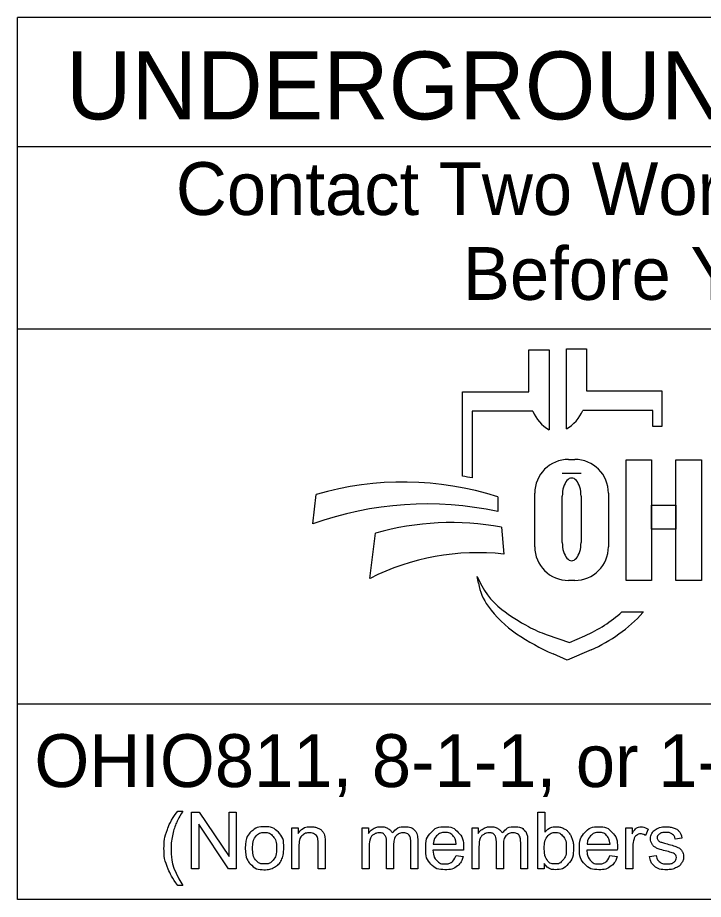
# Model space of a CAD drawing. Extents: x 0 to 72, y -85 to 22.
# Drawn here: x 2.978 to 4.796, y 2.143 to 4.48 of the extents above; entities that cross this region are included whole.
import ezdxf

# ---------------------------------------------------------------- set-up
doc = ezdxf.new("R2010")
doc.units = 0
doc.layers.add('GM_X_Adjacent_County', color=7, linetype='Continuous')
doc.layers.add('GM_X_Township', color=7, linetype='Continuous')

msp = doc.modelspace()

# ---------------------------------------------------------------- linework, layer by layer
at = {"layer": 'GM_X_Adjacent_County'}
for p, q in [((4.3335, 3.4883), (4.3335, 3.5998)), ((4.3335, 3.5998), (4.3872, 3.5998)), ((4.3872, 3.5998), (4.3872, 3.3877)), ((4.4329, 3.39), (4.4329, 3.6021)), ((4.4329, 3.6021), (4.4865, 3.6021)), ((4.4865, 3.6021), (4.4865, 3.4906)), ((4.1576, 3.2644), (4.1576, 3.4883)), ((4.1576, 3.4883), (4.3335, 3.4883)), ((4.4865, 3.4906), (4.6857, 3.4906)), ((4.6857, 3.4906), (4.6857, 3.3968)), ((4.1828, 3.4369), (4.1828, 3.26)), ((4.3439, 3.4369), (4.1828, 3.4369)), ((4.6625, 3.4392), (4.4761, 3.4392)), ((4.6625, 3.3968), (4.6625, 3.4392)), ((4.6857, 3.3968), (4.6625, 3.3968)), ((4.4385, 3.3091), (4.4551, 3.3091)), ((4.4718, 3.2721), (4.422, 3.2721)), ((3.7602, 3.1381), (3.7696, 3.2162)), ((4.2509, 3.2097), (4.2509, 3.1709)), ((4.3491, 3.0776), (4.3491, 3.2196)), ((4.422, 3.089), (4.422, 3.2114)), ((4.4718, 3.2114), (4.4718, 3.089)), ((4.5445, 3.2196), (4.5445, 3.0776)), ((3.912, 2.9936), (3.9267, 3.1137)), ((4.2608, 3.1291), (4.2671, 3.0582)), ((4.1997, 2.9807), (4.1967, 2.9986)), ((4.4551, 2.9882), (4.4385, 2.9882)), ((4.58, 2.9048), (4.6375, 2.9048)), ((4.3816, 2.8444), (4.441, 2.8239)), ((4.441, 2.8239), (4.4821, 2.8417)), ((4.435, 2.7769), (4.3976, 2.7934)), ((4.4983, 2.8044), (4.435, 2.7769))]:
    msp.add_line(p, q, dxfattribs=at)
for points in [[(4.591, 3.3081), (4.6589, 3.3081), (4.6589, 2.9881), (4.591, 2.9881)], [(4.7231, 3.3081), (4.7911, 3.3081), (4.7911, 2.9881), (4.7231, 2.9881)], [(4.6589, 3.1882), (4.7231, 3.1882), (4.7231, 3.1242), (4.6589, 3.1242)]]:
    msp.add_lwpolyline(points, close=True, dxfattribs=at)
for points in [[(3.4021, 2.3766), (3.4153, 2.3766)], [(3.4389, 2.2239), (3.4389, 2.3741), (3.4592, 2.3741), (3.5382, 2.2561), (3.5382, 2.3741), (3.5572, 2.3741), (3.5572, 2.2239), (3.5369, 2.2239), (3.4579, 2.3419), (3.4579, 2.2239), (3.4389, 2.2239)], [(4.3743, 2.2239), (4.3573, 2.2239), (4.3573, 2.3741), (4.3757, 2.3741), (4.3757, 2.3206)], [(3.7048, 2.2239), (3.7048, 2.3328), (3.7214, 2.3328), (3.7214, 2.3173)], [(3.8912, 2.2239), (3.8912, 2.3328), (3.9077, 2.3328), (3.9077, 2.3174)], [(4.1826, 2.2239), (4.1826, 2.3328), (4.1991, 2.3328), (4.1991, 2.3174)], [(4.5904, 2.2239), (4.5904, 2.3328), (4.607, 2.3328), (4.607, 2.3163)], [(4.6495, 2.3293), (4.643, 2.3122)], [(3.7932, 2.2908), (3.7932, 2.2239), (3.7748, 2.2239), (3.7748, 2.2901)], [(3.9743, 2.2871), (3.9743, 2.2239), (3.9559, 2.2239), (3.9559, 2.2946)], [(4.0388, 2.2986), (4.0388, 2.2239), (4.0203, 2.2239), (4.0203, 2.2924)], [(4.2657, 2.2871), (4.2657, 2.2239), (4.2473, 2.2239), (4.2473, 2.2946)], [(4.3301, 2.2986), (4.3301, 2.2239), (4.3117, 2.2239), (4.3117, 2.2924)], [(4.7394, 2.3046), (4.7213, 2.3022)], [(3.7233, 2.2833), (3.7233, 2.2239), (3.7048, 2.2239)], [(3.9097, 2.2803), (3.9097, 2.2239), (3.8912, 2.2239)], [(4.16, 2.2736), (4.0788, 2.2736)], [(4.0799, 2.2887), (4.1406, 2.2887)], [(4.201, 2.2803), (4.201, 2.2239), (4.1826, 2.2239)], [(4.568, 2.2736), (4.4868, 2.2736)], [(4.4879, 2.2887), (4.5486, 2.2887)], [(4.6088, 2.2809), (4.6088, 2.2239), (4.5904, 2.2239)], [(4.1404, 2.2591), (4.1595, 2.2567)], [(4.5484, 2.2591), (4.5675, 2.2567)], [(4.653, 2.2564), (4.6712, 2.2593)], [(4.3743, 2.2375), (4.3743, 2.2239)], [(3.4153, 2.1798), (3.4021, 2.1798)]]:
    msp.add_lwpolyline(points, dxfattribs=at)
for centre, radius, start, end in [((4.4353, 3.4736), 0.0985, 201.9296, 240.7469), ((4.3847, 3.476), 0.0985, 299.2531, 338.0704), ((4.4385, 3.2196), 0.0895, 90, 180), ((4.4551, 3.2196), 0.0895, 0, 90), ((3.9997, 2.4302), 0.8191, 72.1402, 106.3144), ((4.0295, 2.4554), 0.8191, 79.2074, 81.0007), ((4.0628, 2.2991), 0.8919, 77.8238, 109.8274), ((4.1267, 2.4094), 0.7322, 79.44, 105.8467), ((4.4385, 3.0776), 0.0895, 180, 270), ((4.4551, 3.0776), 0.0895, 270, 0), ((4.1987, 2.4262), 0.6357, 83.8248, 116.8021), ((4.3841, 3.0707), 0.2008, 201.0457, 232.5314), ((4.341, 3.0048), 0.1433, 189.6817, 216.0884), ((4.4747, 3.1022), 0.3088, 216.0884, 235.7167), ((4.5766, 3.3219), 0.5173, 232.5314, 241.794), ((4.3387, 3.1722), 0.3602, 293.4582, 312.0712), ((4.3387, 3.1722), 0.401, 293.4582, 317.8286), ((4.4914, 3.1631), 0.3371, 241.794, 250.9821), ((4.6412, 3.3465), 0.6044, 235.7167, 246.2325)]:
    msp.add_arc(centre, radius, start, end, dxfattribs=at)
for centre, start_param, end_param in [((4.4469, 3.2114), 4.712389, 7.853982), ((4.4469, 3.089), 1.570796, 4.712389)]:
    msp.add_ellipse(centre, major_axis=(0, 0.0484), ratio=0.514403, start_param=start_param, end_param=end_param, dxfattribs=at)
for points in [[(3.4021, 2.1798), (3.3869, 2.199), (3.3763, 2.2248), (3.3657, 2.2506), (3.3657, 2.2783), (3.3657, 2.3026), (3.3736, 2.325), (3.3829, 2.3509), (3.4021, 2.3766)], [(3.4153, 2.3766), (3.4029, 2.3553), (3.3989, 2.3462), (3.3927, 2.332), (3.3891, 2.3167), (3.3847, 2.2975), (3.3847, 2.2782), (3.3847, 2.2289), (3.4153, 2.1798)], [(3.5814, 2.2783), (3.5814, 2.3085), (3.5981, 2.3231), (3.6122, 2.3352), (3.6323, 2.3352), (3.6547, 2.3352), (3.669, 2.3205), (3.6832, 2.3058), (3.6832, 2.2799), (3.6832, 2.2589), (3.6769, 2.2469), (3.6706, 2.2348), (3.6586, 2.2282), (3.6466, 2.2215), (3.6323, 2.2215), (3.6095, 2.2215), (3.5954, 2.2362), (3.5814, 2.2508), (3.5814, 2.2783)], [(3.6003, 2.2783), (3.6003, 2.2574), (3.6094, 2.247), (3.6185, 2.2366), (3.6323, 2.2366), (3.646, 2.2366), (3.6551, 2.2471), (3.6642, 2.2575), (3.6642, 2.279), (3.6642, 2.2991), (3.6551, 2.3095), (3.6459, 2.3199), (3.6323, 2.3199), (3.6185, 2.3199), (3.6094, 2.3096), (3.6003, 2.2992), (3.6003, 2.2783)], [(3.7214, 2.3173), (3.7334, 2.3352), (3.756, 2.3352), (3.7659, 2.3352), (3.7741, 2.3316), (3.7823, 2.3281), (3.7864, 2.3224), (3.7905, 2.3166), (3.7922, 2.3087), (3.7932, 2.3036), (3.7932, 2.2908)], [(3.7748, 2.2901), (3.7748, 2.3013), (3.7726, 2.3069), (3.7705, 2.3125), (3.765, 2.3158), (3.7595, 2.3191), (3.7521, 2.3191), (3.7404, 2.3191), (3.7318, 2.3117), (3.7233, 2.3042), (3.7233, 2.2833)], [(3.9077, 2.3174), (3.9128, 2.3254), (3.9214, 2.3303), (3.9299, 2.3352), (3.9407, 2.3352), (3.9528, 2.3352), (3.9606, 2.3301), (3.9683, 2.3251), (3.9715, 2.3161), (3.9844, 2.3352), (4.0051, 2.3352), (4.0213, 2.3352), (4.03, 2.3262), (4.0388, 2.3172), (4.0388, 2.2986)], [(3.9559, 2.2946), (3.9559, 2.3069), (3.9514, 2.313), (3.9469, 2.3191), (3.9366, 2.3191), (3.9288, 2.3191), (3.9222, 2.315), (3.9156, 2.311), (3.9126, 2.3031), (3.9097, 2.2952), (3.9097, 2.2803)], [(4.0203, 2.2924), (4.0203, 2.3035), (4.0185, 2.3083), (4.0168, 2.3132), (4.012, 2.3162), (4.0073, 2.3191), (4.001, 2.3191), (3.9895, 2.3191), (3.9819, 2.3115), (3.9743, 2.3039), (3.9743, 2.2871)], [(4.1595, 2.2567), (4.155, 2.24), (4.1428, 2.2307), (4.1306, 2.2215), (4.1117, 2.2215), (4.0878, 2.2215), (4.0738, 2.2362), (4.0598, 2.2509), (4.0598, 2.2774), (4.0598, 2.3049), (4.074, 2.32), (4.0881, 2.3352), (4.1106, 2.3352), (4.1324, 2.3352), (4.1463, 2.3203), (4.1601, 2.3055), (4.1601, 2.2785), (4.1601, 2.2769), (4.16, 2.2736)], [(4.1406, 2.2887), (4.1394, 2.3025), (4.1337, 2.3094), (4.1249, 2.3201), (4.1108, 2.3201), (4.0981, 2.3201), (4.0894, 2.3115), (4.0808, 2.303), (4.0799, 2.2887)], [(4.1991, 2.3174), (4.2042, 2.3254), (4.2127, 2.3303), (4.2212, 2.3352), (4.2321, 2.3352), (4.2442, 2.3352), (4.2519, 2.3301), (4.2597, 2.3251), (4.2628, 2.3161), (4.2758, 2.3352), (4.2965, 2.3352), (4.3127, 2.3352), (4.3214, 2.3262), (4.3301, 2.3172), (4.3301, 2.2986)], [(4.2473, 2.2946), (4.2473, 2.3069), (4.2428, 2.313), (4.2383, 2.3191), (4.228, 2.3191), (4.2202, 2.3191), (4.2136, 2.315), (4.207, 2.311), (4.204, 2.3031), (4.201, 2.2952), (4.201, 2.2803)], [(4.3117, 2.2924), (4.3117, 2.3035), (4.3099, 2.3083), (4.3081, 2.3132), (4.3034, 2.3162), (4.2987, 2.3191), (4.2923, 2.3191), (4.2809, 2.3191), (4.2733, 2.3115), (4.2657, 2.3039), (4.2657, 2.2871)], [(4.3741, 2.2792), (4.3741, 2.2596), (4.3794, 2.2509), (4.3881, 2.2366), (4.4029, 2.2366), (4.415, 2.2366), (4.4238, 2.2471), (4.4326, 2.2576), (4.4326, 2.2784), (4.4326, 2.2998), (4.4241, 2.3099), (4.4157, 2.3201), (4.4038, 2.3201), (4.3917, 2.3201), (4.3829, 2.3096), (4.3741, 2.299), (4.3741, 2.2792)], [(4.3757, 2.3206), (4.3874, 2.3352), (4.4055, 2.3352), (4.4155, 2.3352), (4.4245, 2.3311), (4.4335, 2.3271), (4.4392, 2.3198), (4.445, 2.3124), (4.4483, 2.3021), (4.4516, 2.2918), (4.4516, 2.28), (4.4516, 2.252), (4.4378, 2.2368), (4.4239, 2.2215), (4.4046, 2.2215), (4.3853, 2.2215), (4.3743, 2.2375)], [(4.5675, 2.2567), (4.563, 2.24), (4.5508, 2.2307), (4.5386, 2.2215), (4.5196, 2.2215), (4.4958, 2.2215), (4.4818, 2.2362), (4.4678, 2.2509), (4.4678, 2.2774), (4.4678, 2.3049), (4.482, 2.32), (4.4961, 2.3352), (4.5186, 2.3352), (4.5404, 2.3352), (4.5543, 2.3203), (4.5681, 2.3055), (4.5681, 2.2785), (4.5681, 2.2769), (4.568, 2.2736)], [(4.5486, 2.2887), (4.5474, 2.3025), (4.5417, 2.3094), (4.5328, 2.3201), (4.5188, 2.3201), (4.5061, 2.3201), (4.4974, 2.3115), (4.4888, 2.303), (4.4879, 2.2887)], [(4.607, 2.3163), (4.6133, 2.3278), (4.6187, 2.3315), (4.6241, 2.3352), (4.6305, 2.3352), (4.6398, 2.3352), (4.6495, 2.3293)], [(4.643, 2.3122), (4.6363, 2.3162), (4.6295, 2.3162), (4.6235, 2.3162), (4.6187, 2.3125), (4.6139, 2.3089), (4.6119, 2.3024), (4.6088, 2.2926), (4.6088, 2.2809)], [(4.7213, 2.3022), (4.7201, 2.3106), (4.7142, 2.3153), (4.7083, 2.3201), (4.6975, 2.3201), (4.6848, 2.3201), (4.6794, 2.3159), (4.6739, 2.3116), (4.6739, 2.306), (4.6739, 2.3024), (4.6762, 2.2995), (4.6785, 2.2966), (4.6833, 2.2946), (4.686, 2.2936), (4.6996, 2.2899), (4.7192, 2.2847), (4.7269, 2.2813), (4.7347, 2.278), (4.7391, 2.2717), (4.7435, 2.2653), (4.7435, 2.2559), (4.7435, 2.2467), (4.7381, 2.2386), (4.7327, 2.2304), (4.7226, 2.226), (4.7124, 2.2215), (4.6996, 2.2215), (4.6784, 2.2215), (4.6672, 2.2303), (4.6561, 2.2391), (4.653, 2.2564)], [(4.6712, 2.2593), (4.6727, 2.2483), (4.6798, 2.2425), (4.6868, 2.2366), (4.6995, 2.2366), (4.7122, 2.2366), (4.7184, 2.2418), (4.7245, 2.247), (4.7245, 2.254), (4.7245, 2.2602), (4.7191, 2.2638), (4.7153, 2.2663), (4.7002, 2.2701), (4.6799, 2.2752), (4.672, 2.2789), (4.6642, 2.2827), (4.6601, 2.2893), (4.6561, 2.2959), (4.6561, 2.3038), (4.6561, 2.3111), (4.6594, 2.3173), (4.6628, 2.3235), (4.6685, 2.3276), (4.6728, 2.3308), (4.6803, 2.333), (4.6877, 2.3352), (4.6962, 2.3352), (4.709, 2.3352), (4.7187, 2.3315), (4.7284, 2.3278), (4.733, 2.3215), (4.7377, 2.3152), (4.7394, 2.3046)], [(4.0788, 2.2736), (4.0799, 2.2557), (4.089, 2.2462), (4.0981, 2.2366), (4.1117, 2.2366), (4.1219, 2.2366), (4.1291, 2.242), (4.1362, 2.2473), (4.1404, 2.2591)], [(4.4868, 2.2736), (4.4879, 2.2557), (4.497, 2.2462), (4.5061, 2.2366), (4.5197, 2.2366), (4.5299, 2.2366), (4.537, 2.242), (4.5442, 2.2473), (4.5484, 2.2591)]]:
    msp.add_open_spline(points, degree=3, dxfattribs=at)
at = {"layer": 'GM_X_Township'}
for p, q in [((2.9775, 2.1428), (2.9775, 4.4803)), ((7.2275, 4.4803), (2.9775, 4.4803)), ((2.9775, 4.1387), (7.2275, 4.1387)), ((2.9775, 3.6553), (7.2275, 3.6553)), ((7.2275, 2.6607), (2.9775, 2.6607)), ((7.2275, 2.1428), (2.9775, 2.1428))]:
    msp.add_line(p, q, dxfattribs=at)

# ---------------------------------------------------------------- texts
at = {"layer": 'GM_X_Adjacent_County'}
for s, height, p in [('UNDERGROUND UTILITIES', 0.18, (3.1057, 4.2106)), ('Contact Two Working Days', 0.14, (3.3972, 3.9571)), ('Before You Dig', 0.14, (4.1583, 3.7321)), ('OHIO811, 8-1-1, or 1-800-362-2764', 0.14, (3.022, 2.4406))]:
    msp.add_text(s, height=height, dxfattribs=at).set_placement(p)

doc.saveas('drawing.dxf')
